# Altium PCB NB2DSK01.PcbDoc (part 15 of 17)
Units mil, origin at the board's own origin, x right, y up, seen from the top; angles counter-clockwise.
Board outline 11815 x 6500.03 mil, 8 copper layers (Top Layer, MidLayer1, MidLayer2, GND, PWR, MidLayer3, MidLayer4, Bottom Layer), stack 74.62 mil thick; 798 components, 1002 nets, 3927 pads, 3182 vias.
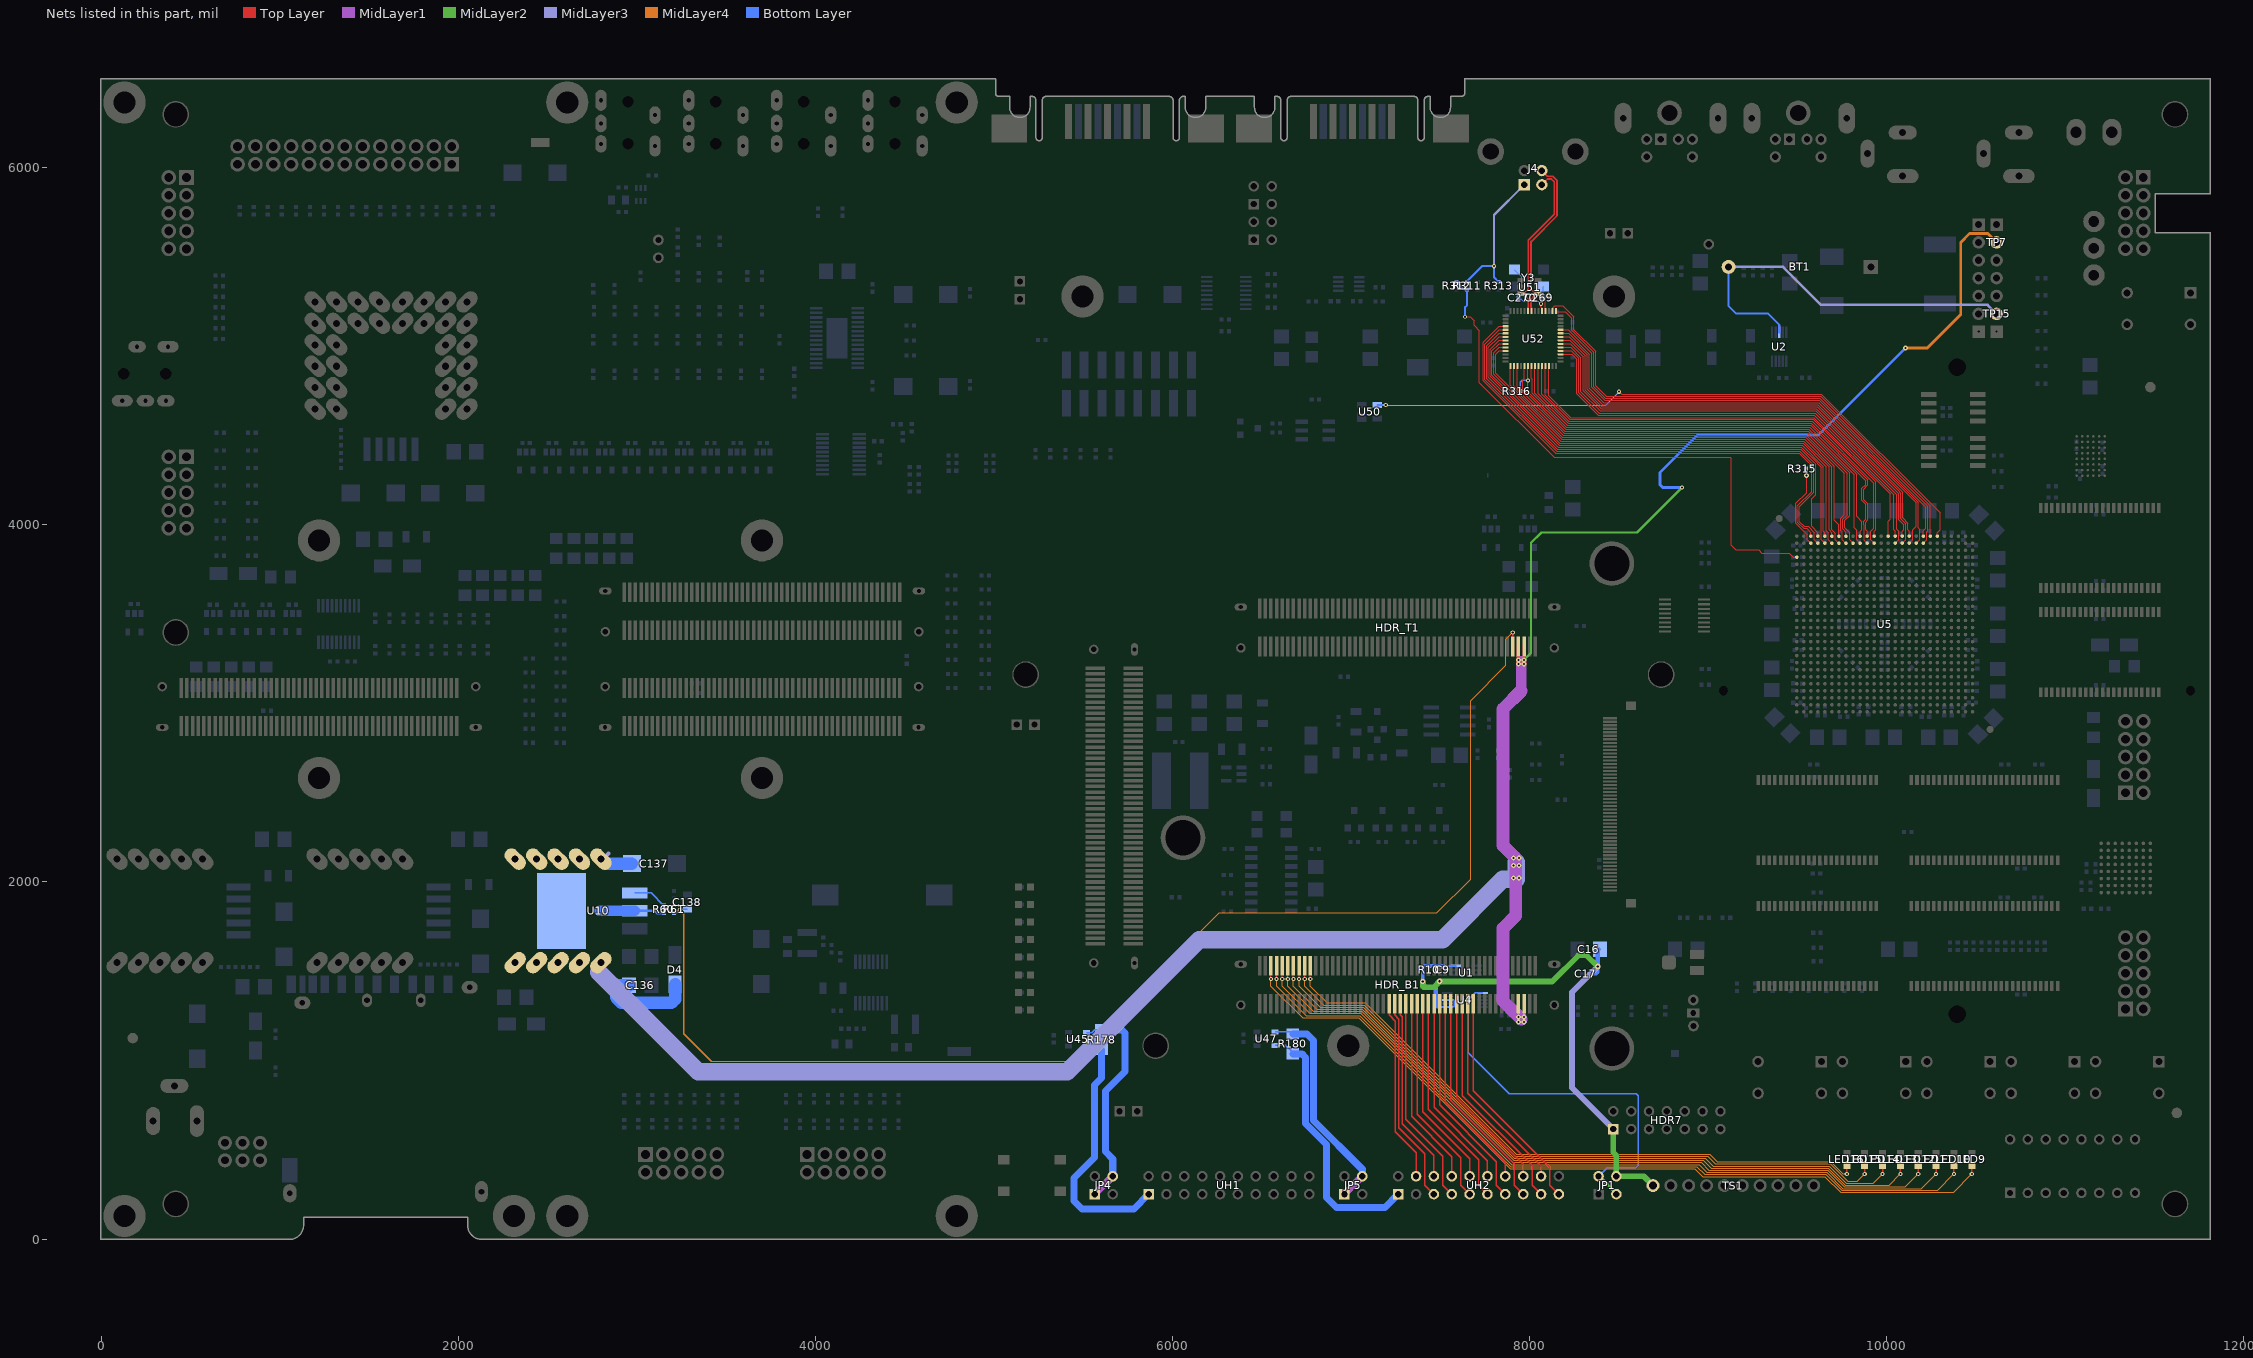
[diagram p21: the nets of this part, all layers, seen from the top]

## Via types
v1: diameter 23.62, hole 11.81, Top Layer to Bottom Layer, tented both sides, 1950 vias
v2: diameter 27.56, hole 11.81, Top Layer to Bottom Layer, tented both sides, 679 vias
v3: diameter 23.62, hole 11.81, Top Layer to Bottom Layer, 194 vias
v4: diameter 31.5, hole 11.81, Top Layer to Bottom Layer, tented both sides, 178 vias
v5: diameter 21.65, hole 11.81, Top Layer to Bottom Layer, tented both sides, 67 vias
v6: diameter 23.62, hole 11.81, Top Layer to Bottom Layer, tented bottom, 53 vias
v7: diameter 26, hole 11.81, Top Layer to Bottom Layer, tented both sides, 21 vias
v8: diameter 26, hole 11.81, Top Layer to Bottom Layer, 13 vias
v9: diameter 28, hole 11.81, Top Layer to Bottom Layer, 8 vias
v10: diameter 25.59, hole 11.81, Top Layer to Bottom Layer, tented both sides, 7 vias
v11: diameter 39.37, hole 11.81, Top Layer to Bottom Layer, tented both sides, 5 vias
v12: diameter 30, hole 11.81, Top Layer to Bottom Layer, 3 vias
v13: diameter 30, hole 11.81, Top Layer to Bottom Layer, tented both sides, 2 vias
v14: diameter 23, hole 11.81, Top Layer to Bottom Layer, tented both sides, 1 vias
v15: diameter 26.56, hole 11.81, Top Layer to Bottom Layer, tented both sides, 1 vias

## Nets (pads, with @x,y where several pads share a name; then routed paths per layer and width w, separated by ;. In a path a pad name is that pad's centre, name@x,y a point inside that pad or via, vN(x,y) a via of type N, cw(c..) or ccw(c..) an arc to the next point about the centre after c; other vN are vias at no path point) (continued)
UIO.IO20: HDR_B1.47 UH2.4 | length 1029.5
  Top Layer w7.87: HDR_B1.47@7212.6,1318.9 7212.6,1255.91 7248.03,1220.47 7248.03,600.19 7363.78,484.44 UH2.4@7363.78,351.97
UIO.IO21: HDR_B1.49 UH2.5 | length 1157.9
  Top Layer w7.87: HDR_B1.49@7244.09,1318.9 7244.09,1255.91 7267.72,1232.28 7267.72,623.82 7413.78,477.75 7413.78,301.97 UH2.5@7463.78,251.97
UIO.IO22: HDR_B1.51 UH2.6 | length 1044.9
  Top Layer w7.87: HDR_B1.51@7275.59,1318.9 7275.59,1255.91 7287.4,1244.1 7287.4,647.44 7463.78,471.06 UH2.6@7463.78,351.97
UIO.IO23: HDR_B1.53 UH2.7 | length 1173.3
  Top Layer w7.87: HDR_B1.53@7307.09,1318.9 7307.09,671.06 7513.78,464.37 7513.78,301.97 UH2.7@7563.78,251.97
UIO.IO24: HDR_B1.55 UH2.8 | length 1060.2
  Top Layer w7.87: HDR_B1.55@7338.58,1318.9 7338.58,686.81 7563.78,461.61 UH2.8@7563.78,351.97
UIO.IO25: HDR_B1.57 UH2.9 | length 1188.6
  Top Layer w7.87: HDR_B1.57@7370.08,1318.9 7370.08,699.85 7613.78,456.15 7613.78,301.97 UH2.9@7663.78,251.97
UIO.IO26: HDR_B1.59 UH2.10 | length 1075.5
  Top Layer w7.87: HDR_B1.59@7401.58,1318.9 7401.58,712.9 7663.78,450.7 UH2.10@7663.78,351.97
UIO.IO27: HDR_B1.61 UH2.11 | length 1203.9
  Top Layer w7.87: HDR_B1.61@7433.07,1318.9 7433.07,725.95 7713.78,445.24 7713.78,301.97 UH2.11@7763.78,251.97
UIO.IO28: HDR_B1.63 UH2.12 | length 1090.9
  Top Layer w7.87: HDR_B1.63@7464.57,1318.9 7464.57,738.99 7763.78,439.78 UH2.12@7763.78,351.97
UIO.IO29: HDR_B1.65 UH2.13 | length 1219.2
  Top Layer w7.87: HDR_B1.65@7496.06,1318.9 7496.06,752.04 7813.78,434.32 7813.78,301.97 UH2.13@7863.78,251.97
UIO.IO30: HDR_B1.67 UH2.14 | length 1106.2
  Top Layer w7.87: HDR_B1.67@7527.56,1318.9 7527.56,765.08 7863.78,428.86 UH2.14@7863.78,351.97
UIO.IO31: HDR_B1.69 UH2.15 | length 1234.6
  Top Layer w7.87: HDR_B1.69@7559.06,1318.9 7559.06,778.13 7913.78,423.41 7913.78,301.97 UH2.15@7963.78,251.97
UIO.IO32: HDR_B1.71 UH2.16 | length 1121.5
  Top Layer w7.87: HDR_B1.71@7590.55,1318.9 7590.55,791.18 7774.45,607.27 7963.78,417.95 UH2.16@7963.78,351.97
UIO.IO33: HDR_B1.73 UH2.17 | length 1249.9
  Top Layer w7.87: HDR_B1.73@7622.05,1318.9 7622.05,804.22 8013.78,412.49 8013.78,301.97 UH2.17@8063.78,251.97
UIO.IO34: HDR_B1.75 UH2.18 | length 1136.9
  Top Layer w7.87: HDR_B1.75@7653.54,1318.9 7653.54,817.27 8063.78,407.03 UH2.18@8063.78,351.97
UIO.IO35: HDR_B1.77 UH2.19 | length 1265.8
  Top Layer w7.87: HDR_B1.77@7685.04,1318.9 7685.04,830.32 8113.78,401.58 8113.78,401.18 ; 8114.17,401.58 8113.78,401.18 ; UH2.19@8163.78,251.97 8113.78,301.97 8113.78,401.18
USB#.DMINUS: J4.2 U51.6 U52.9 | length 889.6
  Top Layer w9.84: U51.6@7968.5,5288.39 7992.13,5264.76 7992.13,5218.37 7990.16,5216.4 U52.9@7990.15,5197.78 U52.9@7990.16,5193.9 ; U51.6@7968.5,5296.26 7992.13,5319.88 7992.13,5593.34 8137.8,5739.01 8137.8,5921.26 8122.05,5937.01 8100,5937.01 J4.2@8068.11,5905.12
USB#.DPLUS: J4.3 U51.1 U52.8 | length 915.5
  Top Layer w9.84: U52.8@8009.84,5193.9 U52.8@8009.84,5197.78 8009.84,5216.4 8007.97,5218.27 8007.97,5264.86 U51.1@8031.5,5288.39 ; U51.1@8031.5,5296.26 8007.97,5319.78 8007.97,5586.71 8153.69,5732.43 8153.69,5927.84 8128.77,5952.76 8099.21,5952.76 J4.3@8068.11,5983.86
USB#.VBUS: J4.1 R311.2 R313.1 | length 816.6
  MidLayer3 w11.81: v1(7800,5448.82) 7800,5735.43 J4.1@7969.69,5905.12
  Bottom Layer w11.81: R311.2@7651.56,5359.75 7651.56,5367.38 7733,5448.82 v1(7800,5448.82) 7800,5386.78 R313.1@7827.02,5359.75
USB.D0: U5.A3 U52.18 | length 2886.5
  Top Layer w5: U52.18@7869.09,5112.2 7865.35,5112.2 7828.74,5112.2 7739,5022.46 7739,4808.25 8146.35,4400.9 9508.55,4400.9 9578.74,4330.71 9578.74,4184.74 9500,4106 9500,4014.14 9533.83,3980.32 9551.18,3980.32 9574.8,3956.69 U5.A3@9574.8,3937.01
USB.D1: U5.B4 U52.19 | length 2919
  Top Layer w5: U52.19@7869.09,5092.52 7865.35,5092.52 7828.74,5092.52 7749,5012.78 7749,4813.99 8150.96,4412.04 9513.16,4412.04 9590.55,4334.65 9590.55,4182.41 9510,4101.86 9510,4018.29 9537.29,3991 9560.18,3991 9594.49,3956.69 9594.49,3917.32 U5.B4@9614.17,3897.64
USB.D2: U5.A4 U52.20 | length 2791
  Top Layer w5: U52.20@7869.09,5072.83 7865.35,5072.83 7828.74,5072.83 7759,5003.09 7759,4819.74 8155.57,4423.17 9517.77,4423.17 9602.36,4338.58 9602.36,4169.29 9578.74,4145.67 9578.74,4019.69 9578.74,4000 9578.74,3992.13 9614.17,3956.69 U5.A4@9614.17,3937.01
USB.D3: U5.B5 U52.21 | length 2799.2
  Top Layer w5: U52.21@7869.09,5053.15 7865.35,5053.15 7828.74,5053.15 7769,4993.41 7769,4825.49 8160.18,4434.31 9522.39,4434.31 9604.29,4352.4 9614.17,4342.52 9633.86,4322.84 9633.86,4019.69 9633.86,4000 9633.86,3917.32 U5.B5@9653.54,3897.64
USB.D4: U5.A5 U52.22 | length 2731.8
  Top Layer w5: U52.22@7869.09,5033.46 7865.35,5033.46 7828.74,5033.46 7779,4983.72 7779,4831.24 8164.8,4445.44 9527,4445.44 9645.67,4326.77 9645.67,4019.69 9645.67,4000 9645.67,3964.57 9653.54,3956.69 U5.A5@9653.54,3937.01
USB.D5: U5.B6 U52.23 | length 2759.5
  Top Layer w5: U52.23@7869.09,5013.78 7865.35,5013.78 7828.74,5013.78 7789,4974.04 7789,4836.98 8169.41,4456.58 9531.61,4456.58 9661.42,4326.77 9661.42,4019.69 9661.42,4000 9661.42,3968.5 9673.23,3956.69 9673.23,3917.32 U5.B6@9692.91,3897.64
USB.D6: U5.A6 U52.24 | length 2692.2
  Top Layer w5: U52.24@7869.09,4994.09 7865.35,4994.09 7828.74,4994.09 7799,4964.35 7799,4842.73 8174.02,4467.71 9536.22,4467.71 9677.17,4326.77 9677.17,4019.69 9677.17,4000 9677.17,3972.44 9692.91,3956.69 U5.A6@9692.91,3937.01
USB.D7: U5.B7 U52.25 | length 2719.9
  Top Layer w5: U52.25@7869.09,4974.41 7865.35,4974.41 7828.74,4974.41 7809,4954.67 7809,4848.48 8178.63,4478.85 9540.84,4478.85 9692.91,4326.77 9692.91,4019.69 9692.91,4000 9692.91,3972.44 9712.6,3952.76 9712.6,3917.32 U5.B7@9732.28,3897.64
USB.D8: U5.A15 U52.45 | length 2542.4
  Top Layer w5: U52.45@8170.28,4954.72 8174.01,4954.72 8236.51,4954.72 8263.78,4927.45 8263.78,4735.5 8385.1,4614.17 9594.49,4614.17 10039.37,4169.29 10039.37,4015.75 10039.37,4000 10039.37,3972.44 10047.24,3964.57 U5.A15@10047.24,3937.01
USB.D9: U5.B15 U52.46 | length 2615.5
  Top Layer w5: U52.46@8170.28,4974.41 8174.01,4974.41 8233.53,4974.41 8275.59,4932.35 8275.59,4740.39 8390,4625.98 9598.43,4625.98 10055.12,4169.29 10055.12,4015.75 10055.12,4000 10055.12,3976.38 10066.93,3964.57 10066.93,3917.32 U5.B15@10047.24,3897.64
USB.D10: U5.A16 U52.47 | length 2600
  Top Layer w5: U52.47@8170.28,4994.09 8174.01,4994.09 8230.55,4994.09 8287.4,4937.24 8287.4,4745.28 8394.89,4637.8 9602.36,4637.8 10066.68,4173.48 10066.68,4029.69 10094.49,4001.89 10094.49,3972.44 10086.61,3964.57 U5.A16@10086.61,3937.01
USB.D11: U5.B16 U52.48 | length 2666.5
  Top Layer w5: U52.48@8170.28,5013.78 8174.01,5013.78 8227.57,5013.78 8299.21,4942.13 8299.21,4750.17 8399.78,4649.61 9606.3,4649.61 10060.41,4195.5 10077.68,4178.23 10077.68,4035.45 10106.3,4006.83 10106.3,3917.32 U5.B16@10086.61,3897.64
USB.D12: U5.A17 U52.49 | length 2644.6
  Top Layer w5: U52.49@8170.28,5033.46 8174.01,5033.46 8224.58,5033.46 8311.02,4947.02 8311.02,4755.07 8404.67,4661.42 9610.24,4661.42 10088.68,4182.97 10088.68,4038.93 10118.11,4009.5 10118.11,3972.44 10125.98,3964.57 U5.A17@10125.98,3937.01
USB.D13: U5.B17 U52.50 | length 2733.4
  Top Layer w5: U52.50@8170.28,5053.15 8174.01,5053.15 8221.6,5053.15 8322.83,4951.92 8322.83,4759.96 8409.56,4673.23 9614.17,4673.23 10164.68,4122.72 10164.68,3991.45 10145.67,3972.44 10145.67,3917.32 U5.B17@10125.98,3897.64
USB.D14: U5.B18 U52.51 | length 2751.8
  Top Layer w5: U52.51@8170.28,5072.83 8174.01,5072.83 8218.62,5072.83 8334.65,4956.81 8334.65,4764.85 8414.46,4685.04 9618.11,4685.04 10175.32,4127.84 10175.32,3983.47 10185.68,3973.1 10185.68,3917.97 U5.B18@10165.35,3897.64
USB.D15: U5.A19 U52.52 | length 2741.7
  Top Layer w5: U52.52@8170.28,5092.52 8174.01,5092.52 8216.54,5092.52 8347.09,4961.96 8347.09,4770.01 8420.25,4696.85 9622.05,4696.85 10219.68,4099.22 10219.68,3981.87 10204.72,3966.91 U5.A19@10204.72,3937.01
USB.FIFOADR0: U5.A11 U52.37 | length 2538
  Top Layer w5: U52.37@8049.21,4885.24 8049.21,4734.25 8215.53,4567.93 9577.74,4567.93 9893.7,4251.97 9893.7,4223.67 9870,4199.97 9870,4141.14 9893.7,4117.44 9893.7,4027.56 9881.89,4015.75 9881.89,4000 9881.89,3972.44 9889.76,3964.57 U5.A11@9889.76,3937.01
USB.FIFOADR1: U5.B12 U52.38 | length 2570.6
  Top Layer w5: U52.38@8068.9,4885.24 8068.9,4730.32 8220.14,4579.07 9582.35,4579.07 9927.01,4234.41 9927.01,3982.13 9921.26,3976.38 9909.45,3964.57 9909.45,3917.32 U5.B12@9929.13,3897.64
USB.FIFOADR2: U5.B11 U52.36 | length 2584
  Top Layer w5: U52.36@8029.53,4885.24 8029.53,4738.19 8210.92,4556.8 9573.12,4556.8 9881.89,4248.03 9881.89,4226 9860,4204.11 9860,4137 9881.89,4115.11 9881.89,4031.5 9870.08,4019.69 9870.08,4000 9870.08,3917.32 U5.B11@9889.76,3897.64
USB.FLAGA: U5.A7 U52.29 | length 2508.6
  Top Layer w5: U52.29@7891.73,4885.24 7891.73,4781.5 8183.25,4489.98 9545.45,4489.98 9706.68,4328.75 9706.68,4025.6 9732.28,4000 U5.A7@9732.28,3937.01
USB.FLAGB: U5.B8 U52.30 | length 2571
  Top Layer w5: U52.30@7911.42,4885.24 7911.42,4777.56 8187.86,4501.12 9550.06,4501.12 9761.69,4289.49 9761.69,4055.47 9743.68,4037.45 9743.68,3968.45 9751.97,3960.17 9751.97,3917.32 U5.B8@9771.65,3897.64
USB.FLAGC: U5.A8 U52.31 | length 2528.5
  Top Layer w5: U52.31@7931.1,4885.24 7931.1,4773.62 8192.47,4512.26 9554.67,4512.26 9777.68,4289.25 9777.68,4054.45 9753.68,4030.45 9753.68,3977.32 9771.65,3959.34 U5.A8@9771.65,3937.01
USB.FLAGD_CS_N: U5.A14 U52.40 | length 2542.8
  Top Layer w5: U52.40@8108.27,4885.24 8108.27,4722.44 8229.37,4601.34 9591.57,4601.34 10019.69,4173.23 10019.69,4031.5 10007.87,4019.69 10007.87,4015.75 10007.87,4000 U5.A14@10007.87,3937.01
USB.IFCLK: R315.1 U5.B3 | length 478.8
  Top Layer w5: v2(9551.18,4275.59) 9551.18,4181.1 9490,4119.92 9490,4010 9535.43,3964.57 9555.12,3944.88 9555.12,3917.32 U5.B3@9574.8,3897.64
  Bottom Layer w5: R315.1@9548.72,4314.95 9548.72,4297.62 9551.18,4295.16 v2(9551.18,4275.59)
USB.INT_N: R316.1 U5.B10 U52.34 | length 2653.3
  Top Layer w5: U52.34@7990.16,4885.24 v1(7990.16,4809.05) 7990.16,4746.06 8201.69,4534.53 9563.9,4534.53 9818.9,4279.53 9818.9,4019.69 9818.9,4000 9818.9,3985.04 9832.68,3971.26 9832.68,3915.35 U5.B10@9850.39,3897.64
  Bottom Layer w7.87: R316.1@7948.35,4748.03 7948.35,4799.5 7957.9,4809.05 v1(7990.16,4809.05)
USB.PKTEND: U5.A12 U52.39 | length 2515.1
  Top Layer w5: U52.39@8088.58,4885.24 8088.58,4726.38 8224.76,4590.2 9586.96,4590.2 9937.01,4240.16 9937.01,4015.75 9937.01,4000 9937.01,3972.44 9929.13,3964.57 U5.A12@9929.13,3937.01
USB.RD_N: U5.B19 U52.1 | length 2904.4
  Top Layer w5: U52.1@8147.64,5193.9 8199.8,5193.9 8236.22,5157.48 8236.22,5088.64 8358.27,4966.59 8358.27,4774.64 8424.24,4708.66 9625.98,4708.66 10230.68,4103.97 10230.68,3967.68 10224.41,3961.41 10224.41,3917.32 U5.B19@10204.72,3897.64
USB.READY: U5.B9 U52.33 | length 2579
  Top Layer w5: U52.33@7970.47,4885.24 7970.47,4820.87 7960.63,4811.02 7960.63,4759.84 8197.08,4523.39 9559.29,4523.39 9791.34,4291.34 9791.34,4052.46 9763.68,4024.8 9763.68,3983.45 9791.34,3955.8 9791.34,3917.32 U5.B9@9811.02,3897.64
USB.RESET_N: U5.A21 U50.3 | length 3601.2
  Top Layer w5: v1(8501,4746) 8514.72,4732.28 9633.86,4732.28 10299.21,4066.93 10299.21,4015.75 10299.21,4000 10299.21,3972.44 10283.46,3956.69 U5.A21@10283.46,3937.01
  MidLayer3 w5: v1(7194.1,4670.93) 8425.93,4670.93 v1(8501,4746)
  Bottom Layer w11.81: U50.3@7146.86,4670.93 v1(7194.1,4670.93)
USB.SLOE: U5.A10 U52.35 | length 2516.3
  Top Layer w5: U52.35@8009.84,4885.24 8009.84,4820.87 8015.75,4814.96 8015.75,4736.22 8206.31,4545.66 9568.51,4545.66 9830.71,4283.47 9830.71,4047.24 9858.27,4019.69 9859.74,4018.21 9859.74,3973.92 9850.39,3964.57 U5.A10@9850.39,3937.01
USB.VBUS: R311.1 R312.1 U5.D1 | length 3121.5
  Top Layer w5: v5(7637.8,5165.36) 7666.64,5165.36 7688.68,5143.32 7688.68,5117 7719,5086.68 7719,4796.75 8137.8,4377.95 9123.15,4377.95 9130,4371.1 9130,3885.1 9155.1,3860 9282,3860 9299.48,3842.52 9417.32,3842.52 9433.07,3842.52 9452.76,3842.52 9476.38,3818.9 U5.D1@9496.06,3818.9
  Bottom Layer w5: R311.1@7649.66,5317.39 R311.1@7651.56,5317.39
  Bottom Layer w11.81: R312.1@7590.54,5359.75 7632.9,5317.39 R311.1@7649.66,5317.39 7649.66,5230.68 7637.8,5218.82 v5(7637.8,5165.36)
USB.WR_N: U5.A20 U52.2 | length 2923.7
  Top Layer w5: U52.2@8127.95,5201.38 8127.95,5214.57 8141.84,5228.45 8184.93,5228.45 8248.03,5165.36 8248.03,5093.53 8370.08,4971.49 8370.08,4779.53 8429.13,4720.47 9629.92,4720.47 10244.09,4106.3 10244.09,4015.75 10244.09,4000 U5.A20@10244.09,3937.01
USB.XTALIN: C270.1 U52.5 Y3.3 | length 362.4
  Top Layer w5: v1(8063.39,5238.58) 8063.39,5221.28 8068.9,5215.77 8068.9,5197.78 U52.5@8068.9,5193.9
  Bottom Layer w5: Y3.3@7914.56,5430.19 7955.71,5389.05 7955.71,5300 7938.94,5283.24 C270.1@7938.94,5272.46 ; C270.1@7943.69,5272.46 7963,5253.15 8048.82,5253.15 v1(8063.39,5238.58)
USB.XTALOUT: C269.1 U52.4 Y3.1 | length 202.9
  Top Layer w5: U52.4@8088.58,5193.9 U52.4@8088.58,5197.78 8088.58,5271.58 v1(8106,5289)
  Bottom Layer w5: Y3.1@8077.56,5335.19 8075.79,5333.42 C269.1@8075.79,5272.46 8092.33,5289 v1(8106,5289)
USER_LED.L0: HDR_B1.6 LED9.1 | length 4607.1
  Top Layer w5: v1(6551.18,1456.69) HDR_B1.6@6551.18,1531.5
  Top Layer w7.87: v1(10476.38,365.24) LED9.1@10476.38,412.48
  MidLayer4 w5: v1(6551.18,1456.69) 6551.18,1417.32 6728.35,1240.16 7043.65,1240.16 7890.11,393.7 8925.2,393.7 8968.5,350.39 9653.54,350.39 9740.94,263 10374.14,263 v1(10476.38,365.24)
USER_LED.L1: HDR_B1.8 LED10.1 | length 4467.3
  Top Layer w5: v1(6582.68,1456.69) HDR_B1.8@6582.68,1531.5
  Top Layer w7.87: v1(10376.38,365.24) LED10.1@10376.38,412.48
  MidLayer4 w5: v1(6582.68,1456.69) 6582.68,1417.32 6748.03,1251.97 7048.55,1251.97 7895,405.51 8937.01,405.51 8980.32,362.21 9658.44,362.21 9747.64,273 10284.14,273 v1(10376.38,365.24)
USER_LED.L2: HDR_B1.10 LED11.1 | length 4327.5
  Top Layer w5: v1(6614.17,1456.69) HDR_B1.10@6614.17,1531.5
  Top Layer w7.87: v1(10276.38,365.24) LED11.1@10276.38,412.48
  MidLayer4 w5: v1(6614.17,1456.69) 6614.17,1417.32 6767.72,1263.78 7053.44,1263.78 7899.9,417.32 8948.82,417.32 8992.13,374.02 9663.33,374.02 9754.34,283 10194.14,283 v1(10276.38,365.24)
USER_LED.L3: HDR_B1.12 LED12.1 | length 4187.8
  Top Layer w5: v1(6645.67,1456.69) HDR_B1.12@6645.67,1531.5
  Top Layer w7.87: v1(10176.38,365.24) LED12.1@10176.38,412.48
  MidLayer4 w5: v1(6645.67,1456.69) 6645.67,1417.32 6787.4,1275.59 7058.33,1275.59 7904.79,429.13 8960.63,429.13 9003.94,385.83 9668.22,385.83 9761.05,293 10104.14,293 v1(10176.38,365.24)
USER_LED.L4: HDR_B1.14 LED13.1 | length 4048
  Top Layer w5: v1(6677.16,1456.69) HDR_B1.14@6677.16,1531.5
  Top Layer w7.87: v1(10076.38,365.24) LED13.1@10076.38,412.48
  MidLayer4 w5: v1(6677.16,1456.69) 6677.16,1417.32 6807.09,1287.4 7063.22,1287.4 7909.68,440.95 8972.44,440.95 9015.75,397.64 9673.11,397.64 9767.75,303 10014.14,303 v1(10076.38,365.24)
USER_LED.L5: HDR_B1.16 LED14.1 | length 3908.2
  Top Layer w5: v1(6708.66,1456.69) HDR_B1.16@6708.66,1531.5
  Top Layer w7.87: v1(9976.38,365.24) LED14.1@9976.38,412.48
  MidLayer4 w5: v1(6708.66,1456.69) 6708.66,1417.32 6826.77,1299.21 7068.12,1299.21 7914.57,452.76 8984.25,452.76 9027.56,409.45 9678,409.45 9774.45,313 9924.14,313 v1(9976.38,365.24)
USER_LED.L6: HDR_B1.18 LED15.1 | length 3768.4
  Top Layer w5: v1(6740.16,1456.69) HDR_B1.18@6740.16,1531.5
  Top Layer w7.87: v1(9876.38,365.24) LED15.1@9876.38,412.48
  MidLayer4 w5: v1(6740.16,1456.69) 6740.16,1417.32 6846.46,1311.02 7073.01,1311.02 7919.47,464.57 8996.06,464.57 9039.37,421.26 9682.9,421.26 9781.16,323 9834.14,323 v1(9876.38,365.24)
USER_LED.L7: HDR_B1.20 LED16.1 | length 3601.9
  Top Layer w5: v1(6771.65,1456.69) HDR_B1.20@6771.65,1531.5
  Top Layer w7.87: v1(9776.38,365.24) LED16.1@9776.38,412.48
  MidLayer4 w5: v1(6771.65,1456.69) 6771.65,1417.32 6866.14,1322.84 7077.9,1322.84 7924.36,476.38 9007.87,476.38 9051.18,433.07 9685.23,433.07 9753.06,365.24 v1(9776.38,365.24)
USERPOWER.AOUT: R178.2 U45.5 UH1.1 | length 1466.9
  Bottom Layer w7.87: U45.5@5519.41,1082.08 5547.33,1082.08 5559.14,1070.27 R178.2@5598.51,1070.27
  Bottom Layer w40: R178.2@5602.45,1062.39 5602.45,903 5563,863.55 5563,457.18 5448.82,343 5448.82,212.6 5492.13,169.29 5783.46,169.29 UH1.1@5866.14,251.97
USERPOWER.BOUT: R180.2 U47.5 UH2.1 | length 1489.2
  Bottom Layer w7.87: U47.5@6575,1085.1 6634.42,1085.1 R180.2@6677.72,1041.8
  Bottom Layer w39.37: R180.2@6673.79,1037.86 6724.14,1037.86 6744.63,1017.37 6744.63,646.62 6862.2,529.05 6862.2,232.28 6917.32,177.17 7188.98,177.17 UH2.1@7263.78,251.97
V_USERA: JP4.1 JP4.4 R178.1 U45.4 | length 1233.5
  MidLayer1 w40: JP4.1@5565.12,251.81 JP4.4@5665.12,351.81
  Bottom Layer w7.87: U45.4@5519.41,1157.08 5547.53,1157.08 5563.08,1172.63 R178.1@5602.45,1172.63
  Bottom Layer w40: R178.1@5602.45,1172.63 5714.37,1172.63 5733,1154 5733,939 5624,830 5624,490.17 5665.12,449.06 JP4.4@5665.12,351.81
V_USERB: JP5.1 JP5.4 R180.1 U47.4 | length 1244.3
  MidLayer1 w40: JP5.1@6962.76,251.81 JP5.4@7062.76,351.81
  Bottom Layer w7.87: U47.4@6575,1160.1 R180.1@6673.59,1160.1
  Bottom Layer w39.37: R180.1@6673.79,1148.09 6753.91,1148.09 6789,1113 6789,665 7062.76,391.24 JP5.4@7062.76,351.81
VBATT: BT1.1 TP15.1 U2.3 | length 2198.2
  MidLayer3 w15: BT1.1@9114.17,5444.88 9419.12,5444.88 9632,5232 10564.91,5232 TP15.1@10614.94,5181.97
  Bottom Layer w11.81: BT1.1@9114.17,5444.88 9114.17,5225.28 9154.56,5184.89 9332.77,5184.89 9397.66,5120 U2.3@9397.66,5078.18
VCCA: C9.1 C16.1 C17.1 HDR7.1 JP1.4 R10.1 TS1.1 U1.8 U4.1 U4.3 | length 4153.4
  MidLayer2 w31.5: v13(7401.5,1443) 7401.5,1427.42 ; v4(8381.13,1526.54) 8318.7,1588.97 8272.72,1588.97 8127.75,1444 ; HDR7.1@8468.5,616.54 8468.5,485.5 8485.83,468.17 JP1.4@8485.83,351.97 8638.7,351.97 TS1.1@8690.67,300 ; 7401.5,1427.42 7417.62,1411.3 ; 7401.5,1427.42 7401.5,1416.1 7406.3,1411.3 7417.62,1411.3 ; 7417.62,1411.3 7463.3,1411.3 ; 7463.3,1411.3 7467.82,1411.3 7498.26,1441.74 8125.49,1441.74 8127.75,1444 ; 7463.3,1411.3 v4(7496,1444) 8127.75,1444
  MidLayer3 w31.5: v4(8381.13,1526.54) 8237.3,1382.72 8237.3,847.74 HDR7.1@8468.5,616.54
  Bottom Layer w7.87: U4.1@7539.38,1300.01 7576.01,1300.01 7579,1303 7579,1335 7574.62,1339.38 U4.3@7539.38,1339.38
  Bottom Layer w12: 7481.91,1305.09 7486.99,1300.01 U4.1@7539.38,1300.01 ; C9.1@7515.53,1530.45 U1.8@7586.54,1530.45
  Bottom Layer w15.75: C17.1@8334.87,1485.2 C17.1@8339.79,1485.2
  Bottom Layer w19.68: C17.1@8334.87,1485.2 8372.83,1485.2 8381.13,1493.5 v4(8381.13,1526.54) ; C16.1@8381.13,1615.13 C16.1@8389,1623
  Bottom Layer w20: v13(7401.5,1443) 7401.5,1522.5 7409.45,1530.45 7436.99,1530.45 7514.54,1530.45 C9.1@7515.53,1530.45
  Bottom Layer w23.62: v4(8381.13,1526.54) C16.1@8381.13,1615.13
  Bottom Layer w25: 7481.91,1305.09 7473,1314 7473,1421 v4(7496,1444)
VCCX: C136.1 C137.1 D4.1 HDR_B1.93 HDR_B1.95 HDR_T1.93 HDR_T1.95 pad.0@2318.68,1548.45 pad.0@2318.68,2128.45 pad.0@2438.68,1548.45 pad.0@2438.68,2128.45 pad.0@2558.68,1548.45 pad.0@2558.68,2128.45 pad.0@2678.68,1548.45 pad.0@2678.68,2128.45 pad.0@2798.68,1548.45 pad.0@2798.68,2128.45 R60.1 TP7.1 U10.2 U10.4 | length 14256.5
  Top Layer w19.68: v2(7937.01,3244.1) HDR_T1.93@7937.01,3318.9 ; v2(7968.5,3244.1) HDR_T1.95@7968.5,3318.9
  Top Layer w25: v2(7937.01,3220.47) v2(7937.01,3244.1) ; v2(7968.5,3220.47) v2(7968.5,3244.1)
  MidLayer1 w23.62: v2(7937.01,1244.1) v2(7937.01,1216.54) v2(7968.5,1216.54) v2(7968.5,1244.1) ; v2(7937.01,3220.47) v2(7937.01,3244.1) 7937.01,3248.03 7968.5,3248.03 v2(7968.5,3244.1) v2(7968.5,3220.47)
  MidLayer1 w59.06: 7952.76,3070.87 7952.76,3220.47 7952.76,3236.22
  MidLayer1 w70.87: 7952.76,1232.28 7938.98,1246.06 7850.39,1334.65 7850.39,1740.16 7921.26,1811.02 7921.26,2023.45 7921.26,2093.45 7921.26,2133.86 7915.36,2139.76 7850.39,2204.73 7850.39,2968.5 7952.76,3070.87
  MidLayer2 w12: v2(7968.5,3244.1) 8006.87,3282.46 8006.87,3898.24 8066.36,3957.73 8601.02,3957.73 v1(8852.79,4209.5)
  MidLayer4 w15.75: v2(10105,4990) 10226.52,4990 10414.6,5178.08 10414.6,5548.6 10414.6,5581.6 10464,5631 10565.91,5631 TP7.1@10614.94,5581.97
  MidLayer3 w22: pad.0@2807.09,2124.41 2841.84,2159.17 ; 2887.8,1398.8 2890.13,1401.13
  MidLayer3 w98.43: pad.0@2787.4,1494.49 3343.44,938.45 5410.9,938.45 6149.61,1677.17 7511.81,1677.17 7850.39,2015.75 7908.68,2015.75 7925.2,2015.75 7925.2,2023.45 7925.2,2093.45 7925.2,2110.24
  Bottom Layer w15.75: U10.2@2988.68,1838.45 3100.29,1838.45 3113.07,1825.67 R60.1@3151.97,1825.67 ; v1(8852.79,4209.5) 8745.5,4209.5 8730,4225 8730,4293.63 8939.24,4502.87 9617.87,4502.87 v2(10105,4990)
  Bottom Layer w60: 2788.94,1838.45 U10.2@2988.68,1838.45
  Bottom Layer w70: pad.0@2781.81,1517.09 2877.64,1421.26 2883.68,1421.26 ; pad.0@2823.97,2103.16 C137.1@2972.62,2103.18 ; 2883.68,1423.45 2883.68,1421.26 ; C136.1@2960.63,1421.26 C136.1@2956.69,1421.26 2883.68,1421.26 ; D4.1@3213.72,1427.17 3213.72,1344.49 3192.68,1323.45 2913.68,1323.45 2883.68,1353.45 2883.68,1421.26
  other v2: 7908.68,2023.45 7940.18,2023.45 7908.68,2093.45 7940.18,2093.45 7909.45,2133.86 7940.95,2133.86
VCCX_REF: C138.2 HDR_T1.91 R60.2 R61.1 U10.1 | length 7503
  Top Layer w7.87: HDR_T1.91@7905.51,3318.9 v1(7905.51,3397.64)
  MidLayer4 w5: 3417.32,996.06 5430.12,996.06 6260.83,1826.77 7480.32,1826.77 7669.29,2015.75 7669.29,3015.75 7866.14,3212.6 7866.14,3358.27 v1(7905.51,3397.64)
  MidLayer4 w7.87: v1(3239.4,1842.3) 3263.68,1818.02 3263.68,1149.7 3417.32,996.06
  Bottom Layer w7.87: U10.1@2988.68,1938.45 3081.55,1938.45 R60.2@3151.97,1868.03 3193.36,1826.64 R61.1@3208.68,1826.64 3224.34,1826.64 3239.7,1842 3246.14,1848.44 C138.2@3283.56,1848.44
VREF_IN: JP1.2 JP1.3 U4.6 | length 2230.8
  MidLayer2 w7.87: JP1.2@8385.83,351.97 JP1.2@8388.7,351.97 ; JP1.3@8487.26,253.41 JP1.3@8490.67,250
  MidLayer2 w20: JP1.2@8388.7,351.97 JP1.3@8487.26,253.41
  Bottom Layer w7.87: U4.6@7736.23,1378.75 7695,1378.75 7653.07,1336.82 7653.07,1047.6 7885.56,815.11 8597.1,815.11 8608.17,804.05 8608.17,414.17 8594,400 8433.86,400 JP1.2@8385.83,351.97
pads on no net: D2.3 D12.3 DAUGHTER_3XCONN.LPA DAUGHTER_3XCONN.LPB DAUGHTER_3XCONN.LPC FD1.0 FD2.0 FD3.0 HDR4.5 HDR4.8 HDR5.5 HDR5.8 J5.2 J5.6 J6.2 J6.6 J7.1 J7.5 J7.8 J10.12 J10.13 J11.12 J11.13 J12.10 J12.11 J12.12 J12.13 J13.10 J13.12 J13.13 J14.12 J14.13 LCD1.MH1 LCD_COVER.TFT_MOUNT MH1.MOUNT MH2.MOUNT MH3.MOUNT MH4.MOUNT MH5.MOUNT MH6.MOUNT MH7.MOUNT MH8.MOUNT PB_MH1.STAND PB_MH2.STAND PB_MH3.STAND PB_MH4.STAND PB_MH5.STAND PB_MH6.STAND PB_MH7.STAND PB_MH8.STAND PB_MH9.STAND PB_MH10.STAND PB_MH11.STAND PB_MH12.STAND PB_MH13.STAND PB_MH14.STAND SW1.1 SW1.2 SW2.1 SW2.2 SW3.1 SW3.2 SW4.1 SW4.2 SW5.1 SW5.2 U3.2 U3.4 U3.7 U3.10 U3.14 U3.15 U5.A23 U5.AA5 U5.AB14 U5.AB15 U5.AB16 U5.AB17 U5.AE6 U5.AF5 U5.AF12 U5.B20 U5.B21 U5.C13 U5.C22 U5.F8 U5.F15 U5.F22 U5.FID1 U5.H16 U5.H22 U5.L1 U5.P2 U5.P20 U5.R20 U5.T2 U5.T20 U5.U20 U5.U22 U5.V2 U5.V20 U5.V22 U5.W15 U5.W20 U5.W22 U5.Y20 U7.A4 U7.A5 U7.A6 U7.B5 U7.C2 U7.C3 U7.C4 U7.C5 U7.D2 U7.D3 U7.D4 U7.D5 U7.E3 U7.E4 U7.E5 U7.F2 U7.F3 U7.F4 U7.G2 U7.H5 U9.5 U9.8 U17.18 U17.25 U19.3 U19.5 U19.6 U24.A1 U24.A8 U24.B1 U24.B4 U24.C1 U24.D1 U24.E1 U24.F8 U24.G1 U24.G8 U24.H1 U24.H8 U25.40 U26.40 U51.3 U51.4 U52.54 VR2.4 VR2.5 VR2.6 Y1.0
copper on no net: | length 5023.2
  Top Layer w5: v1(11299.21,2196.67) 11318.9,2176.99 ; 8811,5216.37 8839.91,5216.37 ; 8811,5216.37 8810.92,5205.77 8839.91,5216.37 ; 8811,5216.37 8810.92,5226.98 8839.91,5216.37 ; 8799,5190.5 8926,5190.5 8926,5243.5 8799,5243.5 8799,5190.5
  Top Layer w7: 8814.45,5212.13 8824.35,5212.13 ; 8814.45,5220.62 8824.35,5220.62
  Top Layer w7.87: v1(9751.97,3759.84) 9771.65,3740.16 ; 10007.87,3110.24 v1(10027.56,3090.55) ; 10047.24,3110.24 v1(10066.93,3090.55) ; 10047.24,3228.35 v1(10066.93,3208.66) ; 10047.24,3740.16 v1(10066.93,3759.84) ; 10086.61,3110.24 v1(10106.3,3090.55) ; 10086.61,3661.42 v1(10106.3,3681.1) ; 10125.98,3110.24 v1(10145.67,3090.55) ; 10244.09,3188.98 v1(10263.78,3169.29) ; 10244.09,3228.35 v1(10263.78,3208.66) ; 10244.09,3267.72 v1(10263.78,3248.03) ; 10244.09,3307.09 v1(10263.78,3287.4) ; 10244.09,3346.46 v1(10263.78,3326.77) ; 10244.09,3385.83 v1(10263.78,3366.14) ; 10244.09,3425.2 v5@10263.78,3405.51 ; 10322.84,3228.35 v1(10342.52,3208.66) ; 10322.84,3267.72 v1(10342.52,3248.03) ; 10322.84,3307.09 v1(10342.52,3287.4) ; 10322.84,3661.42 v1(10342.52,3681.1) ; 10322.83,3858.27 v1(10342.52,3877.95)
  Top Layer w15.75: 6789.49,6259.84 v1(6789.78,5808.9) ; v1(7226,5808.9) 7226.5,6259.84
  MidLayer1 w5: 8811,5163.37 8839.91,5163.37 ; 8811,5163.37 8810.92,5152.77 8839.91,5163.37 ; 8811,5163.37 8810.92,5173.98 8839.91,5163.37 ; 8799,5137.5 8926,5137.5 8926,5190.5 8799,5190.5 8799,5137.5
  MidLayer1 w7: 8814.45,5159.13 8824.35,5159.13 ; 8814.45,5167.62 8824.35,5167.62
  MidLayer2 w5: v1(10342.52,3681.1) 10362.21,3700.79 10539.37,3700.79 ; 8811,5110.37 8839.91,5110.37 ; 8811,5110.37 8810.92,5099.77 8839.91,5110.37 ; 8811,5110.37 8810.92,5120.98 8839.91,5110.37 ; 8799,5084.5 8926,5084.5 8926,5137.5 8799,5137.5 8799,5084.5
  MidLayer2 w7: 8814.45,5106.13 8824.35,5106.13 ; 8814.45,5114.62 8824.35,5114.62
  MidLayer4 w5: 8811,4898.37 8839.91,4898.37 ; 8811,4898.37 8810.92,4887.77 8839.91,4898.37 ; 8811,4898.37 8810.92,4908.98 8839.91,4898.37 ; 8799,4872.5 8799,4925.5 8926,4925.5 8926,4872.5 8799,4872.5
  MidLayer4 w7: 8814.45,4894.13 8824.35,4894.13 ; 8814.45,4902.61 8824.35,4902.61
  MidLayer3 w5: 8811,4951.37 8810.92,4961.98 8839.91,4951.37 ; 8811,4951.37 8810.92,4940.77 8839.91,4951.37 ; 8811,4951.37 8839.91,4951.37 ; 8799,4925.5 8799,4978.5 8926,4978.5 8926,4925.5 8799,4925.5
  MidLayer3 w7: 8814.45,4947.13 8824.35,4947.13 ; 8814.45,4955.61 8824.35,4955.61
  Bottom Layer w5: 377.95,5645.67 387.01,5645.67 ; 477.95,5745.67 484.65,5745.67 ; 8811,4845.37 8839.91,4845.37 ; 8811,4845.37 8810.92,4834.77 8839.91,4845.37 ; 8811,4845.37 8810.92,4855.98 8839.91,4845.37 ; 8799,4819.5 8926,4819.5 8926,4872.5 8799,4872.5 8799,4819.5
  Bottom Layer w7: 8814.45,4841.13 8824.35,4841.13 ; 8814.45,4849.61 8824.35,4849.61
  Bottom Layer w15.75: v1(6953.36,5808.9) 6953.35,6174.79
  other v3: 129.92,43.31 2311.02,43.31 2610.24,43.31 4791.34,43.31 68.68,68.68 191.17,68.68 2249.78,68.68 2372.27,68.68 2548.99,68.68 2671.48,68.68 4730.09,68.68 4852.58,68.68 417.32,110.24 11614.17,110.24 43.31,129.92 216.54,129.92 2224.41,129.92 2397.64,129.92 2523.62,129.92 2696.85,129.92 4704.72,129.92 4877.95,129.92 356.08,135.61 478.57,135.61 11552.93,135.61 11675.42,135.61 68.68,191.17 191.17,191.17 2249.78,191.17 2372.27,191.17 2548.99,191.17 2671.48,191.17 4730.09,191.17 4852.58,191.17 330.71,196.85 503.94,196.85 11527.56,196.85 11700.79,196.85 129.92,216.54 2311.02,216.54 2610.24,216.54 4791.34,216.54 356.08,258.1 478.57,258.1 11552.93,258.1 11675.42,258.1 417.32,283.47 11614.17,283.47 5905.51,996.06 6984.25,996.06 5844.27,1021.43 5966.76,1021.43 6923.01,1021.43 7045.5,1021.43 5818.9,1082.68 5992.13,1082.68 6897.64,1082.68 7070.87,1082.68 5844.27,1143.92 5966.76,1143.92 6923.01,1143.92 7045.5,1143.92 5905.51,1169.29 6984.25,1169.29 1220.47,2496.06 3700.79,2496.06 1159.23,2521.43 1281.72,2521.43 3639.54,2521.43 3762.03,2521.43 1133.86,2582.68 1307.09,2582.68 3614.17,2582.68 3787.4,2582.68 1159.23,2643.92 1281.72,2643.92 3639.54,2643.92 3762.03,2643.92 1220.47,2669.29 3700.79,2669.29 5177.17,3074.8 8736.22,3074.8 5115.92,3100.17 5238.41,3100.17 8674.98,3100.17 8797.47,3100.17 5090.55,3161.42 5263.78,3161.42 8649.61,3161.42 8822.83,3161.42 5115.92,3222.66 5238.41,3222.66 8674.98,3222.66 8797.47,3222.66 5177.17,3248.03 8736.22,3248.03 417.32,3311.02 356.08,3336.39 478.57,3336.39 330.71,3397.64 503.94,3397.64 356.08,3458.88 478.57,3458.88 417.32,3484.25 1220.47,3826.77 3700.79,3826.77 1159.23,3852.14 1281.72,3852.14 3639.54,3852.14 3762.03,3852.14 1133.86,3913.39 1307.09,3913.39 3614.17,3913.39 3787.4,3913.39 1159.23,3974.63 1281.72,3974.63 3639.54,3974.63 3762.03,3974.63 1220.47,4000 3700.79,4000 5496.06,5192.91 8472.44,5192.91 5434.82,5218.28 5557.31,5218.28 8411.2,5218.28 8533.69,5218.28 5409.45,5279.53 5582.68,5279.53 8385.83,5279.53 8559.06,5279.53 5434.82,5340.77 5557.31,5340.77 8411.2,5340.77 8533.69,5340.77 5496.06,5366.14 8472.44,5366.14 417.32,6212.6 11614.17,6212.6 356.08,6237.97 478.57,6237.97 11552.93,6237.97 11675.42,6237.97 129.92,6279.53 2610.24,6279.53 4791.34,6279.53 330.71,6299.21 503.94,6299.21 11527.56,6299.21 11700.79,6299.21 68.68,6304.9 191.17,6304.9 2548.99,6304.9 2671.48,6304.9 4730.09,6304.9 4852.58,6304.9 356.08,6360.46 478.57,6360.46 11552.93,6360.46 11675.42,6360.46 43.31,6366.14 216.54,6366.14 2523.62,6366.14 2696.85,6366.14 4704.72,6366.14 4877.95,6366.14 417.32,6385.83 11614.17,6385.83 68.68,6427.39 191.17,6427.39 2548.99,6427.39 2671.48,6427.39 4730.09,6427.39 4852.58,6427.39 129.92,6452.76 2610.24,6452.76 4791.34,6452.76
  other v5: 10263.78,3401.58
  other v12: 1142.5,377.47 1141.52,456.21

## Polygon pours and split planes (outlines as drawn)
GND on Top Layer "MAIN-TL-Q4-GND" (solid, remove dead copper, pour order 1006): 11791.34,3562.99 11791.34,19.69 5905.51,19.69 5905.51,3562.99
GND on Top Layer "MAIN-TL-Q2-GND" (solid, remove dead copper, pour order 1005): 11811.02,6476.38 11811.02,3543.31 5905.51,3543.31 5905.51,6476.38
GND on Top Layer "MAIN-TL-Q1-GND" (solid, remove dead copper, pour order 1004): 19.69,6476.38 19.69,3543.31 5925.2,3543.31 5925.2,6476.38
AGND on Top Layer "1.2V-GND" (solid, remove dead copper, pour order 1000): 4013.68,1008.45 4803.68,1008.45 4803.68,1743.45 4013.68,1743.45
AGND on Top Layer "Top Layer-AGND" (solid, remove dead copper, pour order 1001): 4013.68,1008.45 4803.68,1008.45 4803.68,1743.45 4013.68,1743.45
SHIELD on Top Layer "USB-TL-SHIELD" (solid, pour order 1002): 7618.68,6464.57 7618.68,5437.01 8405.51,5437.01 8405.51,6464.57
GND on Top Layer "MAIN-TL-Q3-GND" (solid, remove dead copper, pour order 1007): 39.37,3562.99 39.37,19.69 5925.2,19.69 5925.2,3562.99
AUGND on Top Layer "AUDIO-TL-AUGND" (solid, pour order 1003): 4919.31,6480.42 4919.31,4645.77 2533.48,4645.77 2533.48,6480.42
GND on MidLayer1 "MAIN-ML1-Q4-GND" (solid, remove dead copper, pour order 1013): 11791.34,3562.99 11791.34,19.69 5905.51,19.69 5905.51,3562.99
GND on MidLayer1 "MAIN-ML1-Q2-GND" (solid, remove dead copper, pour order 1012): 11811.02,6476.38 11811.02,3543.31 5905.51,3543.31 5905.51,6476.38
1V2 on MidLayer1 "FPGAPWR-ML1-1V2" (solid, remove dead copper, pour order 1009): 9936.7,3826.46 9936.7,4000 10039.37,4000 10039.37,3822.84 10275.59,3822.84 10366.14,3732.28 10366.14,3492.13 10543.31,3492.13 10543.31,3393.7 10366.14,3393.7 10366.14,3157.48 10275.59,3066.93 10039.37,3066.93 10039.37,2889.76 9937.01,2889.76 9937.01,3066.93 9700.79,3066.93 9610.24,3157.48 9610.24,3393.7 9433.07,3393.7 9433.07,3496.06 9610.24,3496.06 9610.24,3740.16 9692.91,3822.84
GND on MidLayer1 "MAIN-ML1-Q3-GND" (solid, remove dead copper, pour order 1014): 3.68,3.45 3.68,3588.45 13.68,3598.45 58.68,3643.45 5958.68,3643.45 5958.68,3.45
AUGND on MidLayer1 "AUDIO-ML1-AUGND" (solid, remove dead copper, pour order 1010): 4921.26,6496.06 4921.26,5417.32 5334.65,5003.94 6185.04,5003.94 6185.04,4594.49 2527.56,4594.49 2527.56,6496.06
GND on MidLayer1 "MAIN-ML1-Q1-GND" (solid, remove dead copper, pour order 1011): 19.69,6476.38 19.69,3543.31 5925.2,3543.31 5925.2,6476.38
AGND on MidLayer1 "MidLayer1-AGND" (solid, remove dead copper, pour order 1008): 4013.68,1008.45 4803.68,1008.45 4803.68,1743.45 4013.68,1743.45
GND on MidLayer2 "MAIN-ML2-Q4-GND" (solid, remove dead copper, pour order 1020): 11791.34,3562.99 11791.34,19.69 5905.51,19.69 5905.51,3562.99
GND on MidLayer2 "MAIN-ML2-Q2-GND" (solid, remove dead copper, pour order 1019): 11811.02,6476.38 11811.02,3543.31 5905.51,3543.31 5905.51,6476.38
GND on MidLayer2 "MAIN-ML2-Q3-GND" (solid, remove dead copper, pour order 1021): -1.32,3.45 18.68,23.45 18.68,3618.45 5958.68,3618.45 5963.68,3623.45 5923.68,3583.45 5923.68,-11.55
GND on MidLayer2 "MAIN-ML2-Q1-GND" (solid, remove dead copper, pour order 1018): 19.69,6476.38 19.69,3543.31 5925.2,3543.31 5925.2,6476.38
AGND on MidLayer2 "MidLayer2-AGND" (solid, remove dead copper, pour order 1016): 4013.68,1008.45 4803.68,1008.45 4803.68,1743.45 4013.68,1743.45
AUGND on MidLayer2 "AUDIO-ML2-AUGND" (solid, pour order 1017): 4921.26,6496.06 4921.26,4661.42 2527.56,4661.42 2527.56,6496.06
2V5 on MidLayer2 "MidLayer2-2V5" (solid, pour order 1015): 9250,4100 9550,4100 9550,3900 9250,3900
GND on MidLayer4 "MAIN-ML3-Q4-GND" (solid, remove dead copper, pour order 1027): 11791.34,3562.99 11791.34,19.69 5905.51,19.69 5905.51,3562.99
GND on MidLayer4 "MAIN-ML3-Q1-GND" (solid, remove dead copper, pour order 1026): 11811.02,6476.38 11811.02,3543.31 5905.51,3543.31 5905.51,6476.38
GND on MidLayer4 "MidLayer3-GND" (solid, remove dead copper, pour order 1028): -1.32,3.45 -1.32,3573.45 5968.68,3573.45 5968.68,3.45
GND on MidLayer4 "MAIN-ML3-Q1-GND" (solid, remove dead copper, pour order 1025): 19.69,6476.38 19.69,3543.31 5925.2,3543.31 5925.2,6476.38
AGND on MidLayer4 "MidLayer3-AGND" (solid, remove dead copper, pour order 1022): 4013.68,1008.45 4803.68,1008.45 4803.68,1743.45 4013.68,1743.45
AUGND on MidLayer4 "AUDIO-ML3-AUGND" (solid, pour order 1024): 4921.26,6496.06 4921.26,4661.42 2527.56,4661.42 2527.56,6496.06
ADC_GND on MidLayer4 "BottomOverlay-ADC_GND" (solid, pour order 1023): 9250,550 9247.24,547.24 7953.6,547.24 7350,1150.84 7350,1650 7539.76,1650 7638.24,1748.48 7639.76,1750 8650,1750 8650,1550 8850,1350 8850,1300 8850,1150 8950,1050 9250,750 9250,650
GND on MidLayer3 "MAIN-ML4-Q4-GND" (solid, remove dead copper, pour order 1034): 11791.34,3562.99 11791.34,19.69 5905.51,19.69 5905.51,3562.99
GND on MidLayer3 "MAIN-ML4-Q3-GND" (solid, remove dead copper, pour order 1035): 39.37,3562.99 39.37,19.69 5925.2,19.69 5925.2,3562.99
GND on MidLayer3 "MAIN-ML4-Q2-GND" (solid, remove dead copper, pour order 1033): 11811.02,6476.38 11811.02,3543.31 5905.51,3543.31 5905.51,6476.38
AUGND on MidLayer3 "AUDIO-ML4-AUGND" (solid, pour order 1031): 4921.26,6496.06 4921.26,4661.42 2527.56,4661.42 2527.56,6496.06
GND on MidLayer3 "MAIN-ML4-Q1-GND" (solid, remove dead copper, pour order 1032): 19.69,6476.38 19.69,3543.31 5925.2,3543.31 5925.2,6476.38
AGND on MidLayer3 "1V2 Regulator" (solid, remove dead copper, pour order 1029): 4013.68,1008.45 4013.68,1743.45 4803.68,1743.45 4803.68,1008.45
1V2 on MidLayer3 "FPGAPWR-ML1-1V2" (solid, remove dead copper, pour order 1030): 10725,4250 10725,2700 9200,2700 9200,4250
GND on Bottom Layer "MAIN-BL-Q4-GND" (solid, remove dead copper, pour order 1046): 11791.34,3562.99 11791.34,19.69 5905.51,19.69 5905.51,3562.99
GND on Bottom Layer "MAIN-BL-Q3-GND" (solid, remove dead copper, pour order 1045): 39.37,3562.99 39.37,19.69 5925.2,19.69 5925.2,3562.99
GND on Bottom Layer "MAIN-BL-Q2-GND" (solid, remove dead copper, pour order 1044): 11811.02,6476.38 11811.02,3543.31 5905.51,3543.31 5905.51,6476.38
GND on Bottom Layer "MAIN-BL-Q1-GND" (solid, remove dead copper, pour order 1043): 19.69,6476.38 19.69,3543.31 5925.2,3543.31 5925.2,6476.38
2V5 on Bottom Layer "Bottom Layer-2V5 3" (solid, remove dead copper, pour order 1036): 9418.68,4028.45 9418.68,3898.45 10558.68,3898.45 10558.68,4028.45
2V5 on Bottom Layer "Bottom Layer-2V5" (solid, remove dead copper, pour order 1038): 9403.68,2863.45 9538.68,2863.45 9538.68,4143.45 9403.68,4143.45
GND on Bottom Layer "FPGA-GND" (solid, remove dead copper, pour order 1041): 9555.12,3877.95 10421.26,3877.95 10421.4,3877.82 10421.4,3011.94 9555.25,3011.94 9555.12,3011.81
2V5 on Bottom Layer "Bottom Layer-2V5 1" (solid, remove dead copper, pour order 1037): 9403.68,2863.45 10568.68,2863.45 10568.68,2993.45 9403.68,2993.45
2V5 on Bottom Layer "Bottom Layer-2V5 2" (solid, remove dead copper, pour order 1039): 10568.68,2863.45 10438.68,2863.45 10438.68,4148.45 10683.68,4148.45 10683.68,3948.45 10568.68,3948.45
AUGND on Bottom Layer "AUDIO-BL-AUGND" (solid, remove dead copper, pour order 1042): 4921.26,6429.13 4921.26,4594.49 2346.46,4594.49 2346.46,6429.13
AGND on Bottom Layer "1V2 Regulator GND" (solid, remove dead copper, pour order 1040): 4013.68,1008.45 4803.68,1008.45 4803.68,1743.45 4013.68,1743.45
no net on Top Overlay "Boundary-No Net" (solid): 145,5969 268,5931 145,5893 156,5918 44,5918 44,5944 156,5944 145,5969
no net on Top Overlay "Boundary-No Net" (solid): 11642.26,5969.39 11765.26,5931.39 11642.26,5893.39 11653.26,5918.39 11541.26,5918.39 11541.26,5944.39 11653.26,5944.39 11642.26,5969.39
no net on Top Overlay "BottomOverlay-No Net" (solid, pour order 1047): 762.87,135 1004.87,135 1004.87,224
GND on GND (split plane): 369 vertices, not listed, extent 18.11,18.05 11792.91,6477.95
GND on GND (split plane): 5098.73,806.5 5100.73,805.67 5102.44,804.36 5103.75,802.65 5104.57,800.66 5104.85,798.52 5104.57,796.38 5103.75,794.39 5102.44,792.68 5100.73,791.37 5098.73,790.54 5096.6,790.26 5094.46,790.54 5092.47,791.37 5090.76,792.68 5089.44,794.39 5088.62,796.38 5088.34,798.52 5088.62,800.66 5089.44,802.65 5090.76,804.36 5092.47,805.67 5094.46,806.5 5096.6,806.78
3V3 on PWR (split plane): 291 vertices, not listed, extent 606.71,201.1 11506.9,5763.37
5V0 on PWR (split plane): 310 vertices, not listed, extent 18.11,18.11 11260.65,6477.95
SHIELD on PWR (split plane): 498 vertices, not listed, extent 809.1,18.05 11792.91,6477.95
5VUSW on PWR (split plane): 10959.25,5470.79 10970.25,5459.79 10973.3,5457.29 10976.77,5455.43 10980.54,5454.29 10984.46,5453.9 10988.38,5454.29 10990.42,5454.91 11260.65,5454.91 11260.65,5331.26 11260.65,5312.1 9607.1,5312.1 9607.1,5508.9 10921.14,5508.9
no net on PWR (split plane): 5098.73,806.5 5100.73,805.67 5102.44,804.36 5103.75,802.65 5104.57,800.66 5104.85,798.52 5104.57,796.38 5103.75,794.39 5102.44,792.68 5100.73,791.37 5098.73,790.54 5096.6,790.26 5094.46,790.54 5092.47,791.37 5090.76,792.68 5089.44,794.39 5088.62,796.38 5088.34,798.52 5088.62,800.66 5089.44,802.65 5090.76,804.36 5092.47,805.67 5094.46,806.5 5096.6,806.78
no net on Keep-Out Layer "MidLayer2-No Net" (solid, pour order 1048): 163 vertices, not listed, extent 4997.55,6140 7647,6496.06

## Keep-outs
Keep-Out Layer:
  rectangle: 8792,4812.5 8933,5249.5
  region: 11811.61,5856.42 11501.78,5856.42 11501.78,5634.92 11811.61,5634.92
  region: 10538.73,115.58 10519.19,111.58 10538.73,107.58 10538.73,115.58
  region: 10538.73,125.58 10519.19,121.58 10538.73,117.58 10538.73,125.58
  region: 10538.73,135.58 10519.19,131.58 10538.73,127.58 10538.73,135.58
  region: 10538.73,145.58 10519.19,141.58 10538.73,137.58 10538.73,145.58
  region: 10538.73,155.58 10519.19,151.58 10538.73,147.58 10538.73,155.58
  region: 10538.86,165.45 10519.32,161.45 10538.86,157.45 10538.86,165.45
  region: 10538.73,175.58 10519.19,171.58 10538.73,167.58 10538.73,175.58
  region: 10538.73,185.58 10519.19,181.58 10538.73,177.58 10538.73,185.58
  region: 10538.73,195.58 10519.19,191.58 10538.73,187.58 10538.73,195.58
  region: 10538.67,205.58 10519.14,201.58 10538.67,197.58 10538.67,205.58
  region: 10047.28,115.58 10066.81,111.58 10047.28,107.58 10047.28,115.58
  region: 10047.28,125.58 10066.81,121.58 10047.28,117.58 10047.28,125.58
  region: 10047.28,135.58 10066.81,131.58 10047.28,127.58 10047.28,135.58
  region: 10047.28,145.58 10066.81,141.58 10047.28,137.58 10047.28,145.58
  region: 10047.28,155.58 10066.81,151.58 10047.28,147.58 10047.28,155.58
  region: 10047.15,165.45 10066.68,161.45 10047.15,157.45 10047.15,165.45
  region: 10047.28,175.58 10066.81,171.58 10047.28,167.58 10047.28,175.58
  region: 10047.28,185.58 10066.81,181.58 10047.28,177.58 10047.28,185.58
  region: 10047.28,195.58 10066.81,191.58 10047.28,187.58 10047.28,195.58
  region: 10047.33,205.58 10066.87,201.58 10047.33,197.58 10047.33,205.58
  lines w8: 4997.55,6496.02 4997.55,6417.32 ccw(c5026.43,6417.32) 5026.43,6388.44 ; 5026.47,6388.44 5076.48,6388.44 5076.48,6338.63 ; 5076.48,6338.58 ccw(c5144.74,6338.58) 5212.99,6338.58 5212.99,6388.44 ; 5213.44,6388.44 cw(c5213.44,6377.95) 5223.92,6377.99 5223.92,6169.29 ccw(c5252.81,6169.29) 5281.69,6169.29 5281.69,6377.95 cw(c5292.18,6377.95) 5292.18,6388.44 5981.15,6388.44 cw(c5981.15,6377.95) 5991.64,6377.95 5991.64,6169.29 ccw(c6020.52,6169.29) 6049.4,6169.24 ; 6049.4,6169.29 6049.4,6377.95 cw(c6059.89,6377.95) 6059.89,6388.44 ; 6060.34,6338.58 ccw(c6128.59,6338.58) 6196.85,6338.58 6196.85,6388.44 6447.7,6388.44 6447.7,6338.63 ; 6060.34,6338.63 6060.34,6388.44 ; 6447.7,6338.58 ccw(c6515.95,6338.58) 6584.2,6338.58 6584.2,6388.44 ; 6584.65,6388.44 cw(c6584.65,6377.95) 6595.14,6377.99 6595.14,6169.29 ccw(c6624.02,6169.29) 6652.9,6169.29 6652.9,6377.95 cw(c6663.39,6377.95) 6663.39,6388.44 7352.37,6388.44 cw(c7352.37,6377.95) 7362.85,6377.95 7362.85,6169.34 ccw(c7391.74,6169.29) 7420.62,6169.29 7420.62,6377.95 cw(c7431.11,6377.95) 7431.11,6388.44 ; 7431.56,6338.58 ccw(c7499.81,6338.58) 7568.06,6338.58 7568.06,6388.44 7618.07,6388.44 ccw(c7618.11,6417.32) 7647,6417.32 ; 7431.56,6338.63 7431.56,6388.44 ; 7647,6417.37 7647,6496.06
  lines w19.68: 11801.29,5634.92 11501.78,5634.92 11501.78,5856.42 11801.45,5856.42
  lines w20: 1052.94,0.46 0.46,0.46 0.46,6495.61 11810.57,6495.61 11810.57,0.45 2132.88,0.45 ; 1053.39,0 ccw(c1053.39,78.74) 1132.13,78.74 1132.13,123.45 2053.68,123.45 2053.68,78.74 ccw(c2132.42,78.74) 2132.42,0

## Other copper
Top Layer:
  rectangle net GND: 10508,95 10550,215
  rectangle net GND: 10035,99 10077,219
  rectangle: 6747.21,6233 6831.77,6379
  rectangle net NetJ7_4: 6856.47,6233 6941.02,6379
  rectangle net GND: 6965.72,6233 7050.27,6379
  rectangle net CAN#.CAN_L: 7074.97,6233 7159.53,6379
  rectangle: 7184.22,6233 7268.78,6379
  rectangle net RS232#.DCD: 5813.01,6233 5897.57,6379
  rectangle net RS232#.RXD: 5703.76,6233 5788.31,6379
  rectangle net RS232#.TXD: 5594.5,6233 5679.06,6379
  rectangle net RS232#.DCD: 5485.25,6233 5569.81,6379
  rectangle net GND: 5376,6233 5460.56,6379
  region net SHIELD: 7673.54,6144.98 7261.2,6144.98 7261.2,5937.4 7673.54,5937.4
  region net SHIELD: 7673.54,6388.98 7569.54,6388.98 7569.54,5966.98 7673.54,5966.98
  rectangle net SHIELD: 6342.21,5966.98 6446.21,6388.98
  region net SHIELD: 6302.33,6388 6198.33,6388 6198.33,5966 6302.33,5966
  rectangle net SHIELD: 4971,5966 5075,6388
  rectangle net 5VUSW: 10250,5373 10348,5506
  rectangle net GND: 2619.56,5928.28 2656.69,6013.17
  region: 8912,5243.5 8912,5190.5 8926,5190.5 8926,5243.5
  rectangle net 5VUSW: 9643,5304 9741,5439
  region net 5V0: 1171.93,3683.87 1171.93,3709.07 1090.35,3709.07 1090.35,3683.87
  rectangle net SHIELD: 820,190 980,230
  rectangle net GND: 4310,1610 4390,1680
  rectangle net GND: 4590,1030 4680,1250
  rectangle net 5V0: 5950,2710 6040,2770
  rectangle net 5V0: 6000,2430 6040,2770
  rectangle net VCCX: 7890,2000 7960,2160
  region net 5V0: 585.89,1329.49 585.89,1364 485,1364 485,1329.49
  rectangle net 3V3: 887.52,3810 912.72,4530
  rectangle net 3V3: 710,5020 735.2,5120
  rectangle net 3V3: 709.76,5200 734.96,5360
  rectangle net 5V0: 2200,5930 2410,6020
  rectangle net 5V0: 10970,5770 11180,5930
  rectangle net 3V3: 7850,3850 7920,3940
  rectangle net 9V0: 7500,2850 7600,2950
  rectangle net 3V3: 6851.54,2045.15 6876.73,2115.15
  rectangle net 1V2: 912.6,3242.68 937.8,3324.25
  rectangle net 1V8: 814.17,3242.68 839.37,3324.25
  rectangle net 2V5: 715.75,3242.68 740.94,3324.25
  rectangle net 3V3: 617.32,3242.68 642.52,3324.25
  rectangle net 3V3: 2930.32,3965.12 2955.51,4046.69
  rectangle net 2V5: 2733.46,3965.12 2758.66,4046.69
  rectangle net 1V2: 2635.04,3965.12 2660.24,4046.69
  rectangle net 5V0: 2536.61,3965.12 2561.81,4046.69
  rectangle net 1V2: 2418.5,3758.43 2443.7,3840
  rectangle net 2V5: 2221.65,3758.43 2246.85,3840
  rectangle net 5V0: 2123.23,3758.43 2148.43,3840
  rectangle net 3V3: 2024.8,3758.43 2050,3840
  rectangle net 5V0: 4300,1100 4400,1270
  rectangle net 3V3: 2100,2020 2150,2150
  rectangle net 3V3: 810,930 940,980
  rectangle net 2V5: 860,1570 910,1760
  rectangle net 3V3: 970,2080 1080,2180
  rectangle net 3V3: 2490,1180 2640,1230
  rectangle net 5V0: 3090,1670 3250,1750
  rectangle net 1V2: 3770,1750 3930,1940
  rectangle net 5V0: 9980,5570 10090,5780
  rectangle net 5V0: 1768.68,3985 1870,4125
  rectangle net GND: 1573.68,3980 1675,4120
  rectangle net 3V3: 1378.68,3980 1480,4120
  rectangle net VCCX: 2248.68,1484.4 2868.68,2195.2
  rectangle net GND: 23.68,1477 643.68,2206.4
  rectangle net GND: 1143.68,1481.7 1763.68,2204.6
  rectangle net DIPSW.D0: 11357.68,96.08 11422.68,188.08
  rectangle net DIPSW.D1: 11257.68,96.08 11322.68,188.08
  rectangle net DIPSW.D2: 11157.68,96.08 11222.68,188.08
  rectangle net DIPSW.D3: 11057.68,96.08 11122.68,188.08
  rectangle net DIPSW.D4: 10957.68,96.08 11022.68,188.08
  rectangle net DIPSW.D5: 10857.68,96.08 10922.68,188.08
  rectangle net DIPSW.D6: 10757.68,96.08 10822.68,188.08
  rectangle net DIPSW.D7: 10657.68,96.08 10722.68,188.08
  rectangle net GND: 502.01,3133.86 521.67,3161.66
  rectangle net GND: 470.51,3133.86 490.18,3161.66
  rectangle net GND: 439.02,3133.86 458.68,3161.66
  region net GND: 970.8,5428.45 970.8,4549 2281.17,4549 2281.17,5428.45
  rectangle net SHIELD: 10091,89 10495,228
  rectangle net AUGND: 3952.76,4755.91 4287.4,5338.58
  region net 5V0: 4278.61,5469.59 4225.42,5469.59 4225.42,5375.42 4278.61,5375.42
  rectangle net VCCX: 7923.34,1202.49 7981.26,1274.2
  region net GND: 6488.19,1373.71 6464.1,1373.71 6464.1,1271.65 6488.19,1271.65
  rectangle net SHIELD: 6342.45,5937.4 6754.79,6144.98
  region net SHIELD: 6302.33,6144.98 5889.99,6144.98 5889.99,5937.4 6302.33,5937.4
  rectangle net SHIELD: 4971.24,5937.4 5383.58,6144.98
  pour cut-out: 11180,2262.5 11510,2262.5 11510,1902.5 11180,1902.5
  pour cut-out: 11050,4510 11240,4510 11240,4260 11050,4260
  pour cut-out: 9460,3980 10520,3980 10520,2920 9460,2920
  pour cut-out: 7874.02,5185.04 7877.95,4905.51 8153.54,4905.51 8149.61,5185.04
  region: 11807.09,1011.81 11732.28,937.01 11732.28,381.89 11807.09,307.09
  region: 11809.8,2126.52 11735,2201.33 11735,2756.45 11809.8,2831.25
  region: 11809.8,3630.47 11735,3705.28 11735,4260.39 11809.8,4335.2
  region: 1822.84,6496.06 1897.64,6421.26 2452.76,6421.26 2527.56,6496.06
  text "TL" at 8850.5,5199.5 h35
MidLayer1:
  region: 8912,5190.5 8912,5137.5 8926,5137.5 8926,5190.5
  rectangle net 1V2: 9319,3879 9392,4110
  rectangle net 1V2: 9319,4043 9562,4110
  rectangle net 9V0: 7363.68,2798.45 7743.68,3088.45
  region net GND: 970.8,5426.84 970.8,4549 2281.17,4549 2281.17,5426.84
  rectangle net AUGND: 3965.55,4765.75 4274.61,5326.77
  rectangle net VCCX: 2228,1458 2873.68,2189
  rectangle net GND: 17,1458 643.68,2208
  rectangle net GND: 1118,1458 1763.68,2189
  text "L1" at 8850.5,5146.5 h35
MidLayer2:
  region: 8912,5137.5 8912,5084.5 8926,5084.5 8926,5137.5
  rectangle net 2V5: 48,3125 309,3433
  rectangle net 2V5: 48,3478 309,3693
  rectangle net 2V5: 48,3428 129,3556
  rectangle net 2V5: 167,3433 205,3567
  rectangle net 2V5: 242,3433 309,3604
  region net GND: 970.8,5426.84 970.8,4549 2281.17,4549 2281.17,5426.84
  rectangle net AUGND: 3965.55,4765.75 4274.61,5326.77
  rectangle net VCCX: 2228,1458 2873.68,2208
  rectangle net GND: 17,1458 643.68,2208
  rectangle net GND: 1118,1458 1763.68,2208
  text "L2" at 8850.5,5093.5 h35
MidLayer4:
  region: 8912,4925.5 8912,4872.5 8926,4872.5 8926,4925.5
  rectangle net 1V2: 9968,4035 10154,4121
  rectangle net GND: 1118,1458 1763.68,2208
  rectangle net 5V0: 5952.6,2403.01 6292.18,2764
  rectangle net AUGND: 3965.55,4765.75 4274.61,5326.77
  region net GND: 970.8,5426.84 970.8,4549 2281.17,4549 2281.17,5426.84
  rectangle net GND: 17,1458 643.68,2208
  rectangle net VCCX: 2228,1458 2873.68,2208
  rectangle net 9V0: 7363.68,2798.45 7657.6,3088.45
  text "L4" at 8850.5,4881.5 h35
